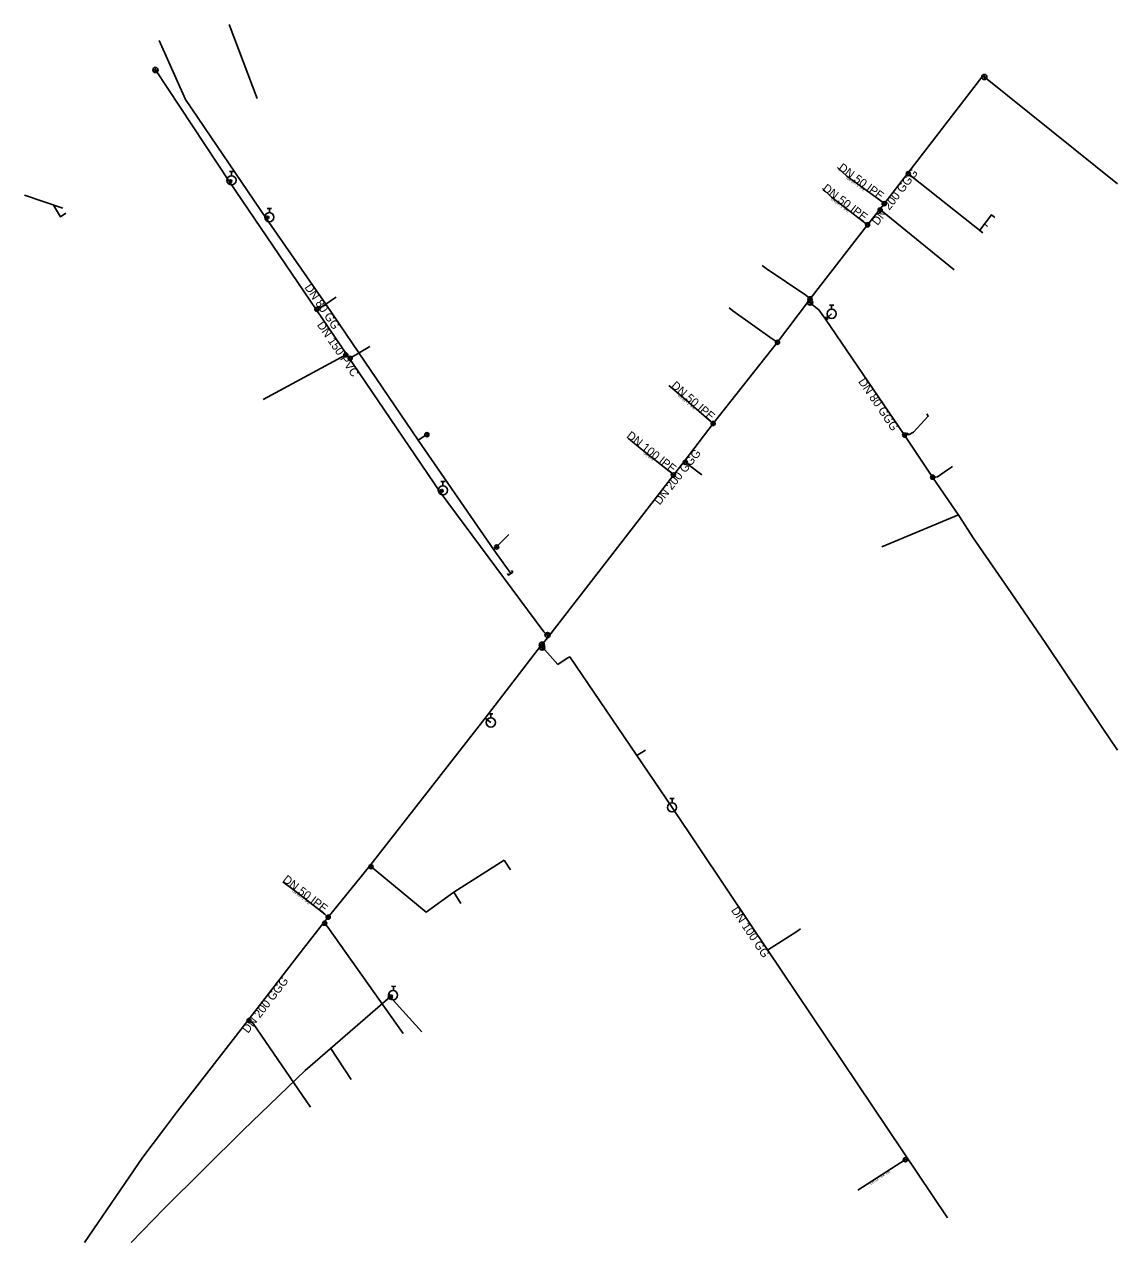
# Model space of a CAD drawing. Extents: x -464787 to -464577, y -1094414 to -1094180.
import ezdxf

# ---------------------------------------------------------------- set-up
doc = ezdxf.new("R2010")
doc.units = 0
for name, color, linetype in [('_hydrantova_odbocka_', 7, 'Continuous'), ('_pripojka_prevzato_z_dokumentace_', 7, 'Continuous'), ('_pripojka_priblizne_', 7, 'Continuous'), ('_voda_smvak_prevzato_z_dokumentace_', 7, 'Continuous'), ('_voda_smvak_priblizne_', 7, 'Continuous'), ('_vodovodni_chranicka_', 7, 'Continuous'), ('Default', 7, 'Continuous'), ('MoLevel 27', 7, 'Continuous'), ('MoLevel 28', 7, 'Continuous'), ('MoLevel 32', 7, 'Continuous'), ('MoLevel 43', 7, 'Continuous'), ('MoLevel 46', 7, 'Continuous'), ('MoLevel 53', 7, 'Continuous'), ('MoLevel 55', 7, 'Continuous'), ('MoLevel 60', 7, 'Continuous')]:
    doc.layers.add(name, color=color, linetype=linetype)

# ---------------------------------------------------------------- blocks, each defined once
blk = doc.blocks.new('_uzaver_')
at = {"layer": 'Default'}
for p, q in [((-0.000035, -0.000035), (0.000035, 0.000035)), ((0.000035, -0.000035), (-0.000035, 0.000035))]:
    blk.add_line(p, q, dxfattribs=at)
for radius in [0.00005, 0.0000025]:
    blk.add_circle((0, 0), radius, dxfattribs=at)
blk = doc.blocks.new('_uzaver_pripojka_')
at = {"layer": 'Default'}
for p, q in [((-0.000035, -0.000035), (0.000035, 0.000035)), ((0.000035, -0.000035), (-0.000035, 0.000035))]:
    blk.add_line(p, q, dxfattribs=at)
for radius in [0.00005, 0.0000025]:
    blk.add_circle((0, 0), radius, dxfattribs=at)
blk = doc.blocks.new('_hydrant_voda_')
at = {"layer": 'Default'}
for p, q in [((-0.000023, 0.000095), (0.000023, 0.000095)), ((0, 0.000095), (0, 0.00005))]:
    blk.add_line(p, q, dxfattribs=at)
blk.add_circle((0, 0), 0.00005, dxfattribs=at)
blk = doc.blocks.new('_zaslepeni_')
at = {"layer": 'Default'}
blk.add_lwpolyline([(-0.00004, -0.00005), (0, -0.00005), (0, 0.00005), (-0.00004, 0.00005), (-0.00004, 0.00005)], dxfattribs=at)

msp = doc.modelspace()

# ---------------------------------------------------------------- linework, layer by layer
at = {"layer": '_hydrantova_odbocka_'}
msp.add_line((-464698.74, -1094313.1), (-464697.67, -1094313.91), dxfattribs=at)
for points in [[(-464747.91, -1094209.91), (-464747.72, -1094209.8), (-464747.53, -1094209.63)], [(-464740.82, -1094217.03), (-464740.6, -1094216.78), (-464740.25, -1094216.73)], [(-464633.31, -1094236.36), (-464633.11, -1094236.18), (-464632.12, -1094235.3)], [(-464707.39, -1094269.6), (-464707.1, -1094269.35), (-464706.88, -1094269.25)]]:
    msp.add_lwpolyline(points, dxfattribs=at)
at = {"layer": '_pripojka_prevzato_z_dokumentace_'}
for p, q in [((-464636.27, -1094232.44), (-464637.11, -1094231.75)), ((-464642.53, -1094240.78), (-464643.55, -1094240.11)), ((-464657.07, -1094266.29), (-464659.7, -1094264.3))]:
    msp.add_line(p, q, dxfattribs=at)
for points in [[(-464622.01, -1094214.14), (-464622.24, -1094213.92), (-464629.17, -1094208.83), (-464631.02, -1094207.15)], [(-464617.5, -1094208.25), (-464617.38, -1094208.34), (-464616.94, -1094208.67)], [(-464625.21, -1094218.18), (-464625.49, -1094217.97), (-464632.14, -1094212.89), (-464633.89, -1094211.2)], [(-464622.92, -1094215.28), (-464622.8, -1094215.36), (-464622.36, -1094215.65)], [(-464654.91, -1094256.41), (-464655.24, -1094256.12), (-464661.09, -1094251.07), (-464663.4, -1094249.08)], [(-464618.08, -1094258.64), (-464617.62, -1094258.26), (-464617.37, -1094258.57), (-464616.38, -1094258.07)], [(-464662.55, -1094266.32), (-464663.34, -1094265.57), (-464668.56, -1094261.47), (-464671.2, -1094259.27)], [(-464660.47, -1094263.7), (-464660.26, -1094263.87), (-464659.7, -1094264.3)], [(-464612.7, -1094266.74), (-464612.52, -1094266.61), (-464612.14, -1094266.72), (-464611.74, -1094266.67)], [(-464720.92, -1094341.48), (-464720.71, -1094341.64), (-464719.74, -1094342.43)], [(-464728.93, -1094351.36), (-464729.57, -1094350.77), (-464735.7, -1094346.03), (-464737.68, -1094344.59)], [(-464729.79, -1094352.41), (-464729.63, -1094352.53), (-464729.01, -1094353.26)], [(-464744.33, -1094371.15), (-464744.18, -1094371.24), (-464743.34, -1094371.81)]]:
    msp.add_lwpolyline(points, dxfattribs=at)
at = {"layer": '_pripojka_priblizne_'}
for p, q in [((-464742.57, -1094193.9), (-464748.01, -1094179.63)), ((-464616.94, -1094208.67), (-464603.02, -1094219.74)), ((-464779.97, -1094214.98), (-464787.36, -1094212.51)), ((-464622.36, -1094215.65), (-464608.54, -1094226.85)), ((-464602.12, -1094218.51), (-464602.7, -1094217.98)), ((-464607.74, -1094274), (-464622.5, -1094280.14)), ((-464667.92, -1094319.21), (-464669.59, -1094320.27)), ((-464704.76, -1094346.58), (-464695.08, -1094340.37)), ((-464695.08, -1094340.37), (-464693.86, -1094342.24)), ((-464704.76, -1094346.58), (-464703.45, -1094348.71)), ((-464729.01, -1094353.26), (-464714.53, -1094373.76)), ((-464716.99, -1094366.71), (-464710.96, -1094373.39)), ((-464743.34, -1094371.81), (-464732.35, -1094387.9)), ((-464728.45, -1094376.62), (-464724.5, -1094382.57))]:
    msp.add_line(p, q, dxfattribs=at)
for points in [[(-464781.77, -1094214.43), (-464780.43, -1094216.63), (-464779.41, -1094215.94)], [(-464600.77, -1094216.77), (-464601.38, -1094216.25), (-464603.65, -1094219.24)], [(-464637.11, -1094231.75), (-464644.74, -1094226.57), (-464645.5, -1094226.01)], [(-464731.22, -1094234.5), (-464731.11, -1094234.46), (-464729.42, -1094233.45), (-464727.72, -1094232.3), (-464727.39, -1094232.1)], [(-464643.55, -1094240.11), (-464651.1, -1094234.75), (-464651.86, -1094234.18)], [(-464724.82, -1094243.92), (-464724.71, -1094243.86), (-464720.92, -1094241.58)], [(-464741.42, -1094251.81), (-464725.55, -1094243.2), (-464725.39, -1094243.08)], [(-464613.82, -1094254.55), (-464613.54, -1094255.01), (-464616.38, -1094258.07)], [(-464711.65, -1094259.62), (-464709.96, -1094258.54), (-464709.58, -1094258.27)], [(-464611.74, -1094266.67), (-464609.83, -1094265.34), (-464608.9, -1094264.66)], [(-464697.08, -1094280.72), (-464696.54, -1094280.16), (-464694.23, -1094277.77)], [(-464719.74, -1094342.43), (-464710.08, -1094350.37), (-464704.76, -1094346.58)], [(-464644.45, -1094357.7), (-464638.79, -1094354.13), (-464638.09, -1094353.62)], [(-464617.56, -1094397.73), (-464617.94, -1094398), (-464627.11, -1094403.86)]]:
    msp.add_lwpolyline(points, dxfattribs=at)
at = {"layer": '_voda_smvak_prevzato_z_dokumentace_'}
for p, q in [((-464747.91, -1094209.91), (-464762.15, -1094188.4)), ((-464602.56, -1094189.92), (-464577.13, -1094210.28)), ((-464707.39, -1094269.6), (-464747.91, -1094209.91)), ((-464636.59, -1094232.86), (-464636.27, -1094233.13)), ((-464636.27, -1094233.13), (-464636.12, -1094233.33)), ((-464687.48, -1094296.49), (-464707.39, -1094269.6)), ((-464687.85, -1094298.95), (-464686.5, -1094297.3)), ((-464686.75, -1094297.1), (-464687.48, -1094296.49)), ((-464686.5, -1094297.3), (-464686.75, -1094297.1)), ((-464698.74, -1094313.1), (-464688.1, -1094299.25)), ((-464688.1, -1094299.25), (-464687.85, -1094298.95)), ((-464688.1, -1094299.25), (-464687.8, -1094299.5)), ((-464687.8, -1094299.5), (-464687.26, -1094299.94))]:
    msp.add_line(p, q, dxfattribs=at)
for points in [[(-464761.44, -1094182.76), (-464756.35, -1094194.11), (-464740.82, -1094217.03)], [(-464636.59, -1094232.86), (-464636.27, -1094232.44), (-464625.21, -1094218.18), (-464622.92, -1094215.28), (-464622.01, -1094214.13), (-464617.5, -1094208.25), (-464603.02, -1094189.55)], [(-464740.82, -1094217.03), (-464729.42, -1094233.45), (-464723.06, -1094242.81), (-464711.65, -1094259.62), (-464697.08, -1094280.72), (-464693.84, -1094285.28)], [(-464686.5, -1094297.3), (-464662.55, -1094266.32), (-464660.47, -1094263.7), (-464654.91, -1094256.41), (-464642.53, -1094240.78), (-464636.59, -1094232.86)], [(-464577.13, -1094319.27), (-464580.22, -1094314.71), (-464590.92, -1094298.73), (-464597.62, -1094288.97), (-464604.88, -1094278.37), (-464607.55, -1094274.29), (-464612.7, -1094266.74), (-464618.08, -1094258.64), (-464626.17, -1094246.8), (-464633.31, -1094236.36), (-464634.56, -1094234.53), (-464636.12, -1094233.33)], [(-464682.95, -1094301.55), (-464682.48, -1094301.29), (-464662.81, -1094330.24)], [(-464775.77, -1094413.97), (-464764.6, -1094397.55), (-464760.61, -1094392.29), (-464757.9, -1094388.69), (-464744.33, -1094371.15), (-464733.7, -1094357.4), (-464729.79, -1094352.41), (-464728.93, -1094351.36), (-464720.92, -1094341.48), (-464698.74, -1094313.1)], [(-464662.81, -1094330.24), (-464647.5, -1094353.16), (-464609.87, -1094409.18)], [(-464766.82, -1094413.97), (-464760.51, -1094407.39), (-464745.31, -1094392.35), (-464733.34, -1094380.85), (-464716.99, -1094366.71), (-464716.48, -1094366.36)]]:
    msp.add_lwpolyline(points, dxfattribs=at)
at = {"layer": '_voda_smvak_priblizne_'}
msp.add_lwpolyline([(-464687.26, -1094299.94), (-464684.78, -1094302.76), (-464682.95, -1094301.55)], dxfattribs=at)
at = {"layer": '_vodovodni_chranicka_'}
for p, q in [((-464622.24, -1094213.92), (-464629.17, -1094208.83)), ((-464625.49, -1094217.97), (-464632.14, -1094212.89)), ((-464655.24, -1094256.12), (-464661.09, -1094251.07)), ((-464663.34, -1094265.57), (-464668.56, -1094261.47)), ((-464729.57, -1094350.77), (-464735.7, -1094346.03))]:
    msp.add_line(p, q, dxfattribs=at)

# ---------------------------------------------------------------- block references
at = {"layer": 'MoLevel 27'}
for p, xscale, yscale, rotation in [((-464762.15, -1094188.4), 10000.000000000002, 10000.000000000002, -56.512345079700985), ((-464602.75, -1094189.76), 9999.999999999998, 10000, -38.754980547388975), ((-464747.72, -1094209.8), 5000, 5000, 43.8982938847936), ((-464740.6, -1094216.78), 5000.000000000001, 5000.000000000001, 8.383248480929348), ((-464636.27, -1094233.13), 9999.999999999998, 10000, -53.32511814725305), ((-464707.1, -1094269.35), 5000.000000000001, 4999.999999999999, 25.155143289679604), ((-464687.85, -1094298.95), 10000, 10000, 51.45216459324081), ((-464686.75, -1094297.1), 10000, 10000, 129.916653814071), ((-464687.8, -1094299.5), 9999.999999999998, 10000, -47.193930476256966)]:
    msp.add_blockref('_uzaver_', p, dxfattribs=dict(at, xscale=xscale, yscale=yscale, rotation=rotation))
at = {"layer": 'MoLevel 27', "xscale": 5000, "yscale": 5000}
msp.add_blockref('_uzaver_', (-464633.11, -1094236.18), dxfattribs=at)
at = {"layer": 'MoLevel 28', "xscale": 17636.68430335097, "yscale": 17636.68430335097}
for p in [(-464747.53, -1094209.63), (-464740.25, -1094216.73), (-464632.12, -1094235.3), (-464706.88, -1094269.25), (-464697.67, -1094313.91), (-464662.81, -1094330.24)]:
    msp.add_blockref('_hydrant_voda_', p, dxfattribs=at)
at = {"layer": 'MoLevel 28', "xscale": 17636.68430335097, "yscale": 17636.684303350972, "rotation": -4.550739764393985}
msp.add_blockref('_hydrant_voda_', (-464716.48, -1094366.36), dxfattribs=at)
at = {"layer": 'MoLevel 43', "xscale": 10000, "yscale": 10000, "rotation": -52.24515426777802}
msp.add_blockref('_zaslepeni_', (-464693.84, -1094285.28), dxfattribs=at)
at = {"layer": 'MoLevel 53', "xscale": 7999.999999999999, "yscale": 7999.999999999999}
for p in [(-464617.38, -1094208.34), (-464622.01, -1094214.13), (-464622.8, -1094215.36), (-464625.21, -1094218.18), (-464636.27, -1094232.44), (-464731.11, -1094234.46), (-464642.53, -1094240.78), (-464725.55, -1094243.2), (-464724.71, -1094243.86), (-464654.91, -1094256.41), (-464709.96, -1094258.54), (-464618.08, -1094258.64), (-464660.26, -1094263.87), (-464662.55, -1094266.32), (-464612.7, -1094266.74), (-464696.54, -1094280.16), (-464720.71, -1094341.64), (-464729.63, -1094352.53), (-464728.93, -1094351.36), (-464716.99, -1094366.71), (-464744.18, -1094371.24), (-464617.94, -1094398)]:
    msp.add_blockref('_uzaver_pripojka_', p, dxfattribs=at)

# ---------------------------------------------------------------- texts
at = {"layer": 'MoLevel 32'}
msp.add_text("DN 32 - 5/4'' PE", height=0.455, rotation=32.6065, dxfattribs=at).set_placement((-464624.58, -1094402.83))
at = {"layer": 'MoLevel 46'}
for s, rotation, p in [('DN 200 GGG', 52.4946, (-464623.28, -1094218.42)), ('DN 80 GG', 304.1748, (-464733.55, -1094230.21)), ('DN 150 PVC', 304.1707, (-464731.16, -1094237.44)), ('DN 80 GGG', 304.3439, (-464627.06, -1094248.35)), ('DN 200 GGG', 51.4713, (-464665.18, -1094272.2)), ('DN 100 GG', 303.8907, (-464651.53, -1094350.04)), ('DN 200 GGG', 52.3026, (-464744.35, -1094373.81))]:
    msp.add_text(s, height=1.605, rotation=rotation, dxfattribs=at).set_placement(p)
at = {"layer": 'MoLevel 55'}
for s, rotation, p in [("DN 25 - 1'' IPE", 323.7032, (-464629.29, -1094209.31)), ("DN 25 - 1'' IPE", 322.6234, (-464632.32, -1094213.33)), ("DN 25 - 1'' IPE", 319.2137, (-464661.74, -1094251.11)), ('DN 80 L', 321.8525, (-464668.36, -1094262.21)), ("DN 25 - 1'' IPE", 322.2871, (-464735.93, -1094346.43))]:
    msp.add_text(s, height=0.455, rotation=rotation, dxfattribs=at).set_placement(p)
at = {"layer": 'MoLevel 60'}
for s, rotation, p in [('DN 50 IPE', 323.7032, (-464630.97, -1094207.51)), ('DN 50 IPE', 322.6452, (-464634.01, -1094211.46)), ('DN 50 IPE', 319.2137, (-464663.11, -1094249.33)), ('DN 100 IPE', 321.8525, (-464671.69, -1094259.01)), ('DN 50 IPE', 322.2871, (-464737.8, -1094344.4))]:
    msp.add_text(s, height=1.605, rotation=rotation, dxfattribs=at).set_placement(p)

doc.saveas('drawing.dxf')
